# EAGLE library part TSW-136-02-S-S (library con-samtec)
THROUGH-HOLE .025" SQ POST HEADER Source: Samtec TSW.pdf
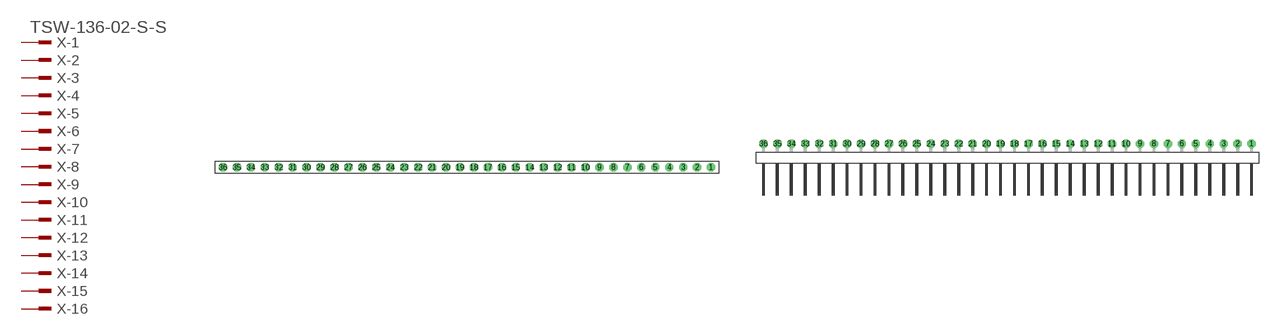
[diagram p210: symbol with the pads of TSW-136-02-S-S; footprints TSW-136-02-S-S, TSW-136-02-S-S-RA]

Designator prefix X; gates -1=MPINV -2=MPIN -3=MPIN -4=MPIN -5=MPIN -6=MPIN -7=MPIN -8=MPIN -9=MPIN -10=MPIN -11=MPIN -12=MPIN -13=MPIN -14=MPIN -15=MPIN -16=MPIN -17=MPIN -18=MPIN -19=MPIN -20=MPIN -21=MPIN -22=MPIN -23=MPIN -24=MPIN -25=MPIN -26=MPIN -27=MPIN -28=MPIN -29=MPIN -30=MPIN -31=MPIN -32=MPIN -33=MPIN -34=MPIN -35=MPIN -36=MPIN

## TSW-136-02-S-S (OC_FARNELL: unknown; OC_NEWARK: unknown)  [TSW-136-02-S-S]
1  -1:1  pas
2  -2:1  pas
3  -3:1  pas
4  -4:1  pas
5  -5:1  pas
6  -6:1  pas
7  -7:1  pas
8  -8:1  pas
9  -9:1  pas
10  -10:1  pas
11  -11:1  pas
12  -12:1  pas
13  -13:1  pas
14  -14:1  pas
15  -15:1  pas
16  -16:1  pas
17  -17:1  pas
18  -18:1  pas
19  -19:1  pas
20  -20:1  pas
21  -21:1  pas
22  -22:1  pas
23  -23:1  pas
24  -24:1  pas
25  -25:1  pas
26  -26:1  pas
27  -27:1  pas
28  -28:1  pas
29  -29:1  pas
30  -30:1  pas
31  -31:1  pas
32  -32:1  pas
33  -33:1  pas
34  -34:1  pas
35  -35:1  pas
36  -36:1  pas

## TSW-136-02-S-S-RA (OC_FARNELL: unknown; OC_NEWARK: unknown)  [TSW-136-02-S-S-RA]
Pads as for TSW-136-02-S-S

## Footprint TSW-136-02-S-S (pad centres in mm)
THROUGH-HOLE .025" SQ POST HEADER Source: Samtec TSW.pdf
drill 1 pad 1.5 octagon: 1 44.45,0; 2 41.91,0; 3 39.37,0; 4 36.83,0; 5 34.29,0; 6 31.75,0; 7 29.21,0; 8 26.67,0; 9 24.13,0; 10 21.59,0; 11 19.05,0; 12 16.51,0; 13 13.97,0; 14 11.43,0; 15 8.89,0; 16 6.35,0; 17 3.81,0; 18 1.27,0; 19 -1.27,0; 20 -3.81,0; 21 -6.35,0; 22 -8.89,0; 23 -11.43,0; 24 -13.97,0; 25 -16.51,0; 26 -19.05,0; 27 -21.59,0; 28 -24.13,0; 29 -26.67,0; 30 -29.21,0; 31 -31.75,0; 32 -34.29,0; 33 -36.83,0; 34 -39.37,0; 35 -41.91,0; 36 -44.45,0

## Footprint TSW-136-02-S-S-RA (pad centres in mm)
THROUGH-HOLE .025" SQ POST HEADER Source: Samtec TSW.pdf
drill 1 pad 1.5 octagon: 1 44.45,1.524; 2 41.91,1.524; 3 39.37,1.524; 4 36.83,1.524; 5 34.29,1.524; 6 31.75,1.524; 7 29.21,1.524; 8 26.67,1.524; 9 24.13,1.524; 10 21.59,1.524; 11 19.05,1.524; 12 16.51,1.524; 13 13.97,1.524; 14 11.43,1.524; 15 8.89,1.524; 16 6.35,1.524; 17 3.81,1.524; 18 1.27,1.524; 19 -1.27,1.524; 20 -3.81,1.524; 21 -6.35,1.524; 22 -8.89,1.524; 23 -11.43,1.524; 24 -13.97,1.524; 25 -16.51,1.524; 26 -19.05,1.524; 27 -21.59,1.524; 28 -24.13,1.524; 29 -26.67,1.524; 30 -29.21,1.524; 31 -31.75,1.524; 32 -34.29,1.524; 33 -36.83,1.524; 34 -39.37,1.524; 35 -41.91,1.524; 36 -44.45,1.524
